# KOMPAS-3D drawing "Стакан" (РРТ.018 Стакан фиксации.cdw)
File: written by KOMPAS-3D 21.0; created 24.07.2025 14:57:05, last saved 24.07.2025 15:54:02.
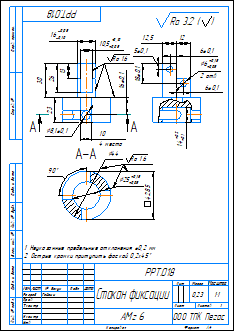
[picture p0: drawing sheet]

Sheet 1: A4, portrait

Document properties: Полное имя файла: ..\Модели КД\РРТ.018 Стакан фиксации.m3d; Автор: User; Знак неуказанной шероховатости: 4; Параметр неуказанной шероховатости: Ra 3.2; Масса: 0.233412

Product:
- Part/product: Стакан
    Масса: 0.233412
    Форматы листов документа: A4
  - Body: Тело 1
      Масса: 0.233227

Title block, sheet 1: Наименование: Стакан фиксации; designation: РРТ.018; Материал: АМг 6; Масса: 0,23; Количество листов документа: 1; organisation: ООО ТПК Пегас; Форматы листов документа: A4; stored path: C:\Users\User\Desktop\Ручной ротатор КД\Чертежи\РРТ.018 Стакан фиксации.cdw; Разработал: Гайсин

Views: Вид 1, Спереди, Проекционный вид 2, Местный разрез 1, Разрез А-А
Referenced files in C:\Users\User\Desktop\Ручной ротатор КД\Модели КД\: РРТ.018 Стакан фиксации.m3d
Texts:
  Стакан
  Ra 3.2
  Ra 3.2 ( )
Dimensions and other numbers on the sheet: 16±0,1; 10,5; 13; 26; 30; 23; 8,1±0,1; 10; 4 места; 7; 12,5; 12; 5±0,1; 6±0,1; 18±0,1; 2 отв; 14; 44; 25; 42,85; 3; 1:1; 1; 0,23

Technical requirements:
  Неуказанные предельные отклонения  0,2 мм
  Острые кромки притупить фаской 0,2х45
